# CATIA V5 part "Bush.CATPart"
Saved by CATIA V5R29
Part number: Bush
Bounding box of the stored display mesh (mm): x 75 to 115, y 10 to 50, z 160 to 220
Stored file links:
  D:\Abhinav\2019\3rd Session\CATIA V5 2019\RESOURCES\CATIA_RESOURCES\Tutorial Files\Tutorials\Tutorials\c12_catia_v5_6r2018_tut\c12_catia_v5_6r2018_tut\c12_catia_v5_6r2018_tut\c12tut2\Bush.CATPart
  E:\_Deepak\2017_Deepak\CATIA\Resources\Tutorial Files\Tutorials\c12_catia_v5_6r2015_tut\c12tut2\Assembly_cat_v5-6r2016.CATProduct
  D:\Abhinav\2019\3rd Session\CATIA V5 2019\RESOURCES\CATIA_RESOURCES\Tutorial Files\Tutorials\Tutorials\c12_catia_v5_6r2018_tut\c12_catia_v5_6r2018_tut\c12_catia_v5_6r2018_tut\c12tut2\Guide Pillar.CATPart
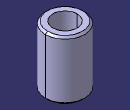
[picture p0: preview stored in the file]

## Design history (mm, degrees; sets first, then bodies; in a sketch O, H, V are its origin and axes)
Set1
  DatumSurface1: linked copy from another document
  DatumCurve1: linked copy from another document
Body1 (main body)
  Sketch1 on face of DatumSurface1, origin (0, 0, 200), H (1, 0, 0), V (0, 1, 0)
    projected circle E1 centre (95, 30) radius 12.5 from edge of DatumCurve1
    circle A1 centre (95, 30) radius 20
    point P1 (95, 30)
    radius A1 = 20
    concentricity: P1 E1, A1 E1
  Pad1: profile Sketch1, direction (0, 0, 1), length 20, opposite side length 40
  Chamfer1: length 2, angle 45, on face of Pad1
